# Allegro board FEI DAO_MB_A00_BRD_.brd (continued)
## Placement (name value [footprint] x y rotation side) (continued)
PC1190  -  [C_0402NEW]  119.39 57.59 180 top
PC1191  -  [C_0402NEW]  119.37 60.69 90 top
PC1192  -  [C_0402NEW]  116.06 59.85 90 top
PC1193  -  [C_0402NEW]  120.13 46.74 270 top
PC1194  -  [C_0402NEW]  121.98 44.97 270 top
PC1195  -  [C_0402NEW]  118.55 44.97 270 top
PC1196  -  [C_0402NEW]  120.44 42.34 270 top
PC1197  -  [C_0402NEW]  117.09 59.13 270 top
PC1198  -  [C_0402NEW]  117.09 57.35 270 top
PC1199  -  [C_0402NEW]  118.55 46.74 270 top
PC1200  -  [C_0402NEW]  120.13 44.97 270 top
PC1201  -  [C_0402NEW]  121.98 46.74 270 top
PC1202  -  [C_0402NEW]  130.17 48.94 90 top
PC1203  -  [C_0402NEW]  127.06 55.44 270 top
PC1204  -  [C_0402NEW]  130.17 53.67 270 top
PC1205  -  [C_0402NEW]  130.17 55.44 270 top
PC1206  -  [C_0402NEW]  128.83 50.81 270 top
PC1207  -  [C_0402NEW]  130.17 51.63 270 top
PC1208  -  [C_0402NEW]  127.12 51.82 270 top
PC1209  -  [C_0402NEW]  127.12 53.6 270 top
PC1210  -  [C_0402NEW]  127.12 50.05 270 top
PC1211  -  [C_0402NEW]  128.86 55.51 270 top
PC1212  -  [C_0402NEW]  128.86 49.06 270 top
PC1213  -  [C_0402NEW]  128.86 53.73 270 top
PC1214  -  [C_0402NEW]  125.63 55.47 270 top
PC1215  -  [C_0402NEW]  125.63 53.69 270 top
PC1216  -  [C_0402NEW]  125.63 51.91 270 top
PC1217  -  [C_0402NEW]  125.63 50.07 270 top
PC1301  -  [C_0402NEW]  26.24 26.64 0 top
PC1302  -  [C_0402NEW]  26.22 24.77 0 top
PC1303  -  [C_0402NEW]  37.56 13.73 90 top
PC1304  -  [C_0402NEW]  37.64 15.58 180 top
PC1305  -  [C_0402NEW]  36.67 14.64 270 top
PC1306  -  [C_0603NEW]  28.63 16.22 270 top
PC1307  -  [C_0402NEW]  38.56 17.04 0 top
PC1309  -  [C_0603NEW]  35.59 15.52 270 top
PC1310  -  [C_0402NEW]  34.12 12.86 180 top
PC1311  -  [C_0603NEW]  29.75 17.93 180 top
PC1312  -  [C_0402NEW]  24.99 27.63 0 top
PC1313  -  [C_0402NEW]  26.24 25.71 0 top
PC1314  -  [C_0805NEW]  20.92 25.37 180 top
PC1315  -  [C_0805NEW]  20.92 23.58 180 top
PC1316  -  [C_0402NEW]  30.42 5.27 270 bottom
PC1317  -  [C_0402NEW]  30.32 15.69 270 top
PC1318  -  [C_0402NEW]  42.83 18.68 90 top
PC1319  -  [C_0402NEW]  33.18 15.28 270 top
PC1320  -  [C_0402NEW]  40.85 19.64 0 top
PC1321  -  [C_0402NEW]  41.94 21.75 270 top
PC1322  -  [C_0402NEW]  23.25 21.17 0 top
PC1323  -  [C_0402NEW]  38.44 23.58 0 top
PC1324  -  [C_0402NEW]  41.38 22.82 180 top
PC1325  -  [C_0402NEW]  40.8 20.84 90 top
PC1326  -  [C_0402NEW]  40.67 17.56 270 top
PC1327  -  [C_0603NEW]  38.46 19.14 0 top
PC1328  -  [C_0402NEW]  39.46 21.62 270 top
PC1329  -  [C_0402NEW]  61.63 8.96 90 bottom
PC1330  -  [C_0805NEW]  63.02 8.46 90 bottom
PC1331  -  [C_0805NEW]  26.13 14.72 180 bottom
PC1332  -  [C_0805NEW]  26.13 12.88 180 bottom
PC1333  -  [C_0402NEW]  29.57 22.63 180 top
PC1334  -  [C_0402NEW]  28.68 20.81 0 top
PC1335  -  [C_0402NEW]  28.66 23.58 0 top
PC1336  -  [C_0402NEW]  32.33 5.27 270 bottom
PC1337  -  [C_0402NEW]  31.36 5.27 270 bottom
PC1338  -  [C_0402NEW]  18.18 11.71 90 bottom
PC1339  -  [C_0402NEW]  9.12 7.64 90 bottom
PC1340  -  [C_0402NEW]  11.13 4.35 0 bottom
PC1341  -  [C_0402NEW]  35.58 5.42 0 top
PC1342  -  [C_0402NEW]  39.83 27.71 0 top
PD4  -  [BAS40CW_SOT323-3]  311.37 6.94 90 top
PD5  -  [PESD24VS2UT_SOT23-3]  55.21 7.11 0 top
PD6  -  [PESD24VS2UT_SOT23-3]  51.21 8.62 180 top
PD7  -  [PESD24VS2UT_SOT23-3]  32.31 83.97 270 top
PD100  -  [LL34]  248.83 12.28 0 bottom
PD1301  -  [RB751V-40_SOD323-2]  36.26 11.64 0 top
PH700  -  [R_0402NEW]  115.26 90.31 90 bottom
PH701  -  [R_0402NEW]  123.68 85.02 90 top
PH702  -  [R_0402NEW]  154.84 76.18 270 bottom
PH703  -  [R_0402NEW]  140.42 68.54 180 bottom
PJP3  -  [JUMP_43X79]  235.35 43.11 180 top
PJP19  -  [JUMP_43X79]  148.99 6.02 0 bottom
PJP20  -  [JUMP_43X118]  133.48 13.63 90 bottom
PJP21  -  [JUMP_43X39]  138.54 3.06 0 bottom
PJP60  -  [JUMP_43X39]  41.59 38.58 180 top
PJP61  -  [JUMP_43X39]  253.14 46.54 0 bottom
PJP62  -  [JUMP_43X39]  31.37 45.4 0 top
PJP101  -  [JUMP_43X118]  221.87 4.68 180 bottom
PJP103  -  [JUMP_43X118]  263.58 12.58 0 bottom
PJP200  -  [JUMP_43X79]  26.19 58.99 270 top
PJP201  -  [JUMP_43X118]  43.91 55.08 180 top
PJP203  -  [JUMP_43X39]  35.87 59.7 90 top
PJP204  -  [JUMP_43X39]  39.15 59.62 180 top
PJP300  -  [JUMP_43X79]  103.98 13.78 270 bottom
PJP301  -  [JUMP_43X79]  94.16 5.8 180 bottom
PJP400  -  [JUMP_43X79]  154.46 73.34 270 top
PJP401  -  [JUMP_43X79]  155.51 48.12 0 bottom
PJP500  -  [JUMP_43X79]  130.06 5.55 180 top
PJP501  -  [JUMP_43X79]  114.13 16.31 270 bottom
PJP502  -  [JUMP_43X79]  115.87 12.1 180 bottom
PJP702  -  [JUMP_43X39]  118.74 88.25 90 top
PJP801  -  [JUMP_43X39]  35.97 24.04 90 top
PJPDC1  -  [ACES_50299-00501-003_5P]  23.2 70.2 180 bottom
PL2  -  [TAIYO_FBMJ4516HS720NT_2P]  58.76 6.63 0 bottom
PL4  -  [MURAT_BLM18BD102SN1D_L0603_2P]  33.9 81.11 180 top
PL5  -  [TAIYO_FBMJ4516HS720NT_2P]  23.15 67.97 180 top
PL6  -  [TAIYO_FBMJ4516HS720NT_2P]  17.3 73.62 0 top
PL15  -  [TAI-T_VMPI0703AR-1R0M-Z01_2P]  139.07 7.77 180 bottom
PL100  -  [TAI-T_HCB2012KF-121T50_2P]  216.62 5.16 90 bottom
PL101  -  [TOKO_FDSD0630-H-4R7M-P3_2P]  261.15 7.45 180 bottom
PL103  -  [TOKO_FDSD0630-H-4R7M-P3_2P]  230.97 8.7 180 bottom
PL200  -  [TAI-T_VMPI0703AR-1R0M-Z01_2P]  23.4 58.59 90 bottom
PL301  -  [TAIYO_NRS4018T1R0NDGJ_2P]  100.29 5.42 0 bottom
PL400  -  [TAI-T_VMPI0703AR-1R0M-Z01_2P]  154.59 58.67 270 bottom
PL500  -  [TAI-T_VMPI0703AR-1R0M-Z01_2P]  120.9 6.07 180 bottom
PL700  -  [TAI-T_HCB2012KF-121T50_2P]  116.66 87.25 90 top
PL702  -  [CYNTE_PDME064T-R36MS1R405_4P]  140.29 65.24 0 bottom
PL704  -  [CYNTE_PDME064T-R36MS1R405_4P]  119.53 85.52 90 bottom
PL1300  -  [TAIYO_NRS4018T1R0NDGJ_2P]  22.93 25.55 0 bottom
PL1301  -  [TOKO_FDSD0630-H-4R7M-P3_2P]  19.33 19.14 0 bottom
PQ2  -  [FDV301N_NL_SOT23-3]  37.37 81.07 180 top
PQ3  -  [MMST3904-7-F_SOT323-3]  34.64 77.24 90 top
PQ4  -  [TP0610K-T1-E3_SOT23-3]  40.85 72.98 90 top
PQ5  -  [FDS6679AZ_SO8]  18.17 65.68 270 bottom
PQ6  -  [L2N7002WT1G_SC70-3]  34.38 72.86 270 top
PQ100  -  [SI7326DN-T1-E3_PAK1212-8]  259.14 10.06 0 top
PQ101  -  [SI7326DN-T1-E3_PAK1212-8]  238.15 7.76 90 bottom
PQ102  -  [SI7326DN-T1-E3_PAK1212-8]  257.41 12.92 180 top
PQ103  -  [SI7326DN-T1-E3_PAK1212-8]  233.84 11.52 0 bottom
PQ104  -  [2N7002DW-T-R7_SOT363-6]  242.18 14.9 270 top
PQ105  -  [DTC115EUA_SC70-3]  244.04 18.5 270 top
PQ200  -  [SI7326DN-T1-E3_PAK1212-8]  24.56 62.93 270 top
PQ210  -  [SI7326DN-T1-E3_PAK1212-8]  29.03 64.56 90 top
PQ400  -  [SI7326DN-T1-E3_PAK1212-8]  155.05 58.25 0 top
PQ405  -  [SI7326DN-T1-E3_PAK1212-8]  154.36 56.6 270 top
PQ500  -  [SI7326DN-T1-E3_PAK1212-8]  120.51 7.3 270 top
PQ501  -  [SI7326DN-T1-E3_PAK1212-8]  116.9 3.85 0 top
PQ704  -  [MDU1516URH_POWERDFN56-8-5]  149.04 70.06 90 bottom
PQ706  -  [SI7170DP-T1-GE3_POWERPAK8-5]  143.1 75.46 0 bottom
PQ708  -  [MDU1516URH_POWERDFN56-8-5]  125 89.18 270 top
PQ710  -  [SI7170DP-T1-GE3_POWERPAK8-5]  124.36 92.21 0 bottom
PQ711  -  [SI7170DP-T1-GE3_POWERPAK8-5]  129.7 91.97 0 bottom
PQ1300  -  [SI7121DN-T1-GE3_POWERPAK8-5]  19 59.42 90 top
PQ1301  -  [FDS6679AZ_SO8]  70.87 8.53 270 bottom
PQ1304  -  [SI7716ADN-T1-GE3_POWERPAK8-5]  22.83 23.58 0 top
PQ1305  -  [SI7716ADN-T1-GE3_POWERPAK8-5]  19.25 21.76 270 top
PQ1306  -  [2N7002DW-T-R7_SOT363-6]  35.11 28.1 270 top
PQ1307  -  [2N7002DW-T-R7_SOT363-6]  44.22 28.91 180 top
PQ1311  -  [2N7002DW-T-R7_SOT363-6]  28.38 74.59 270 top
PR1  -  [R_0402NEW]  311.13 8.85 180 top
PR6  -  [R_0402NEW]  52.69 4.59 180 top
PR7  -  [R_0402NEW]  56.62 5.36 180 top
PR8  -  [R_0402NEW]  49.99 4.59 0 top
PR9  -  [R_0402NEW]  53.93 5.36 0 top
PR11  -  [R_0402NEW]  39.85 80.87 270 top
PR12  -  [R_0402NEW]  40.73 78.18 90 top
PR13  -  [R_0402NEW]  39.85 79.09 270 top
PR14  -  [R_0402NEW]  32.72 79.84 0 top
PR15  -  [R_0402NEW]  36.68 76.22 180 top
PR16  -  [R_0402NEW]  33.64 78.95 180 top
PR17  -  [R_0402NEW]  35.77 77.24 0 top
PR19  -  [R_0402NEW]  35.59 72.27 90 top
PR20  -  [R_0402NEW]  35.9 74.51 0 top
PR21  -  [R_0402NEW]  16.61 69.53 180 top
PR22  -  [R_0402NEW]  14.15 64.67 180 top
PR23  -  [R_0402NEW]  13.83 69.53 0 top
PR24  -  [R_0805NEW]  19.8 70.13 0 top
PR25  -  [R0402_0OHM-NEW]  33.38 74.64 180 top
PR79  -  [R_0402NEW]  143.55 13.04 270 bottom
PR80  -  [R0402_0OHM-NEW]  144.5 13.04 270 bottom
PR82  -  [R_0402NEW]  145.34 13.01 0 bottom
PR83  -  [R0402_0OHM-NEW]  141.89 12.14 90 bottom
PR84  -  [R_0603NEW]  140.94 12.34 180 bottom
PR85  -  [R_1206NEW]  135.35 3.01 180 bottom
PR86  -  [R_0402NEW]  140.63 2.87 90 bottom
PR87  -  [R_0402NEW]  143.1 2.87 90 bottom
PR88  -  [R0402_0OHM-NEW]  141.52 3.78 270 bottom
PR89  -  [R_0402NEW]  144.87 3.78 270 bottom
PR90  -  [R0402_0OHM-NEW]  143.29 14.42 90 bottom
PR91  -  [R0402_0OHM-NEW]  142.4 14.42 90 bottom
PR100  -  [R0402_0OHM-NEW]  252.66 6.17 90 bottom
PR101  -  [R_0402NEW]  251.12 4.38 90 bottom
PR102  -  [R_0402NEW]  247.31 5.29 270 bottom
PR103  -  [R_0402NEW]  250.17 4.38 90 bottom
PR104  -  [R_0402NEW]  249.15 5.29 270 bottom
PR105  -  [R_0402NEW]  250.22 8.26 270 bottom
PR106  -  [R_0402NEW]  247.92 7.35 90 bottom
PR107  -  [R_0603NEW]  254.75 7.91 180 top
PR108  -  [R_0603NEW]  245.2 7.92 180 top
PR109  -  [R_1206NEW]  256.46 12.32 180 bottom
PR110  -  [R_1206NEW]  228.47 13.31 0 bottom
PR111  -  [R_0402NEW]  249.9 15.12 90 top
PR112  -  [R_0402NEW]  244.95 6.87 180 top
PR113  -  [R_0402NEW]  251.5 14.18 180 top
PR114  -  [R_0402NEW]  245.59 15.15 270 top
PR115  -  [R_0402NEW]  246.86 17.79 90 top
PR116  -  [R0402_0OHM-NEW]  247.74 17.79 90 top
PR200  -  [R_0603NEW]  33.39 64.5 0 top
PR201  -  [R_0402NEW]  37.23 69.05 0 top
PR202  -  [R_0603NEW]  42.07 69.99 0 top
PR203  -  [R_1206NEW]  28.83 68.51 0 top
PR204  -  [R_0402NEW]  42.84 68.16 180 top
PR205  -  [R_0402NEW]  42.84 67.08 180 top
PR206  -  [R_0402NEW]  42.91 64.28 180 top
PR232  -  [R0402_0OHM-NEW]  42.91 65.24 180 top
PR236  -  [R0402_0OHM-NEW]  42.91 63.33 180 top
PR237  -  [R_0402NEW]  40.48 61.38 0 top
PR238  -  [R_0402NEW]  42.91 62.44 180 top
PR300  -  [R_0402NEW]  97.43 4.98 0 top
PR301  -  [R_0603NEW]  100.09 2.52 0 bottom
PR302  -  [R_0402NEW]  95.51 3.27 180 bottom
PR303  -  [R_0402NEW]  97.82 2.49 90 top
PR304  -  [R_0402NEW]  97.16 3.29 270 bottom
PR305  -  [R_0402NEW]  93.66 3.29 270 bottom
PR306  -  [R0402_0OHM-NEW]  98.77 2.49 90 top
PR307  -  [R_0402NEW]  124.8 8.47 0 top
PR400  -  [R_0402NEW]  155.69 68.82 270 bottom
PR401  -  [R_0603NEW]  153.7 62.76 270 bottom
PR402  -  [R_0402NEW]  156.58 68.82 270 bottom
PR403  -  [R0402_0OHM-NEW]  161.7 74.2 0 bottom
PR404  -  [R_1206NEW]  159.39 60.89 270 bottom
PR405  -  [R_0402NEW]  159.61 67.89 90 bottom
PR406  -  [R_0402NEW]  158.67 68.82 270 bottom
PR407  -  [R_0402NEW]  157.76 68.81 270 bottom
PR408  -  [R_0402NEW]  161.7 76.04 0 bottom
PR409  -  [R_0402NEW]  161.7 75.12 0 bottom
PR410  -  [R_0402NEW]  72.54 4.72 0 bottom
PR500  -  [R_0402NEW]  128.42 8.66 0 top
PR501  -  [R_0402NEW]  128.69 10.06 180 top
PR502  -  [R_0603NEW]  121.63 9.1 180 top
PR503  -  [R0402_0OHM-NEW]  127.49 8.47 180 top
PR504  -  [R_1206NEW]  124.05 7.34 270 bottom
PR505  -  [R_0402NEW]  127.78 12.79 0 top
PR507  -  [R_0402NEW]  128.69 11.9 180 top
PR508  -  [R0402_0OHM-NEW]  129.56 11.9 0 top
PR510  -  [R_0402NEW]  128.69 10.94 180 top
PR513  -  [R0402_0OHM-NEW]  129.56 11.01 0 top
PR514  -  [R_0402NEW]  129.56 10.06 0 top
PR701  -  [R_0402NEW]  138.52 88.17 270 top
PR702  -  [R_0402NEW]  137.64 92.17 270 bottom
PR703  -  [R_0402NEW]  137.74 89.1 270 bottom
PR704  -  [R_0402NEW]  136.73 90.38 0 bottom
PR705  -  [R_0402NEW]  136.86 86.32 0 bottom
PR707  -  [R_0402NEW]  140.25 92.1 180 bottom
PR708  -  [R_0402NEW]  150.78 80.43 270 bottom
PR709  -  [R_0402NEW]  139.3 91.19 270 bottom
PR710  -  [R_0402NEW]  139.74 89.37 270 bottom
PR711  -  [R_0402NEW]  140.7 89.37 0 bottom
PR712  -  [R_0402NEW]  143.47 86.15 90 top
PR713  -  [R0402_0OHM-NEW]  143.93 93.57 270 bottom
PR714  -  [R0402_0OHM-NEW]  144.62 79.66 270 bottom
PR715  -  [R_0402NEW]  144.37 87.09 270 top
PR716  -  [R0402_0OHM-NEW]  143.83 90.42 270 bottom
PR717  -  [R_0603NEW]  142.27 79.97 270 bottom
PR718  -  [R0402_0OHM-NEW]  144.72 89.57 270 bottom
PR719  -  [R0402_0OHM-NEW]  145.67 89.57 270 bottom
PR720  -  [R_0603NEW]  143.54 78.57 90 bottom
PR721  -  [R0402_0OHM-NEW]  148.23 88.25 180 top
PR722  -  [R_0402NEW]  146.55 90.37 270 bottom
PR723  -  [R0402_0OHM-NEW]  147.5 90.37 270 bottom
PR724  -  [R_0402NEW]  152.52 88.21 90 bottom
PR725  -  [R_0402NEW]  146.2 85.94 0 top
PR726  -  [R0402_0OHM-NEW]  149.89 80.43 270 bottom
PR727  -  [R_0402NEW]  146.2 86.83 0 top
PR728  -  [R_0402NEW]  151.67 80.43 270 bottom
PR729  -  [R_0402NEW]  142.12 90.28 90 bottom
PR730  -  [R_0402NEW]  143.4 88.66 90 top
PR732  -  [R0402_0OHM-NEW]  149.78 89.94 180 bottom
PR735  -  [R_0402NEW]  144.72 88.66 90 top
PR736  -  [R_0402NEW]  153.13 82.69 90 bottom
PR737  -  [R_0402NEW]  145.67 88.66 90 top
PR740  -  [R_0402NEW]  151.34 83.59 0 bottom
PR741  -  [R_0402NEW]  150.48 83.59 180 bottom
PR742  -  [R_0402NEW]  150.4 82.73 270 top
PR744  -  [R_0402NEW]  150.45 83.65 0 top
PR746  -  [R_0402NEW]  149.84 88.22 180 bottom
PR747  -  [R_0402NEW]  150.72 89.13 270 bottom
PR749  -  [R_0603NEW]  148.81 79.27 90 bottom
PR750  -  [R_0402NEW]  150.86 86.45 180 bottom
PR751  -  [R_1206NEW]  140.52 76.01 90 bottom
PR754  -  [R_0402NEW]  149.94 87.34 0 bottom
PR755  -  [R_0603NEW]  154.86 88.63 270 bottom
PR757  -  [R_0402NEW]  153.64 86.43 90 bottom
PR758  -  [R_0603NEW]  139.1 93.24 180 bottom
PR759  -  [R_0402NEW]  143.03 93.57 270 bottom
PR760  -  [R_1206NEW]  127.69 84.52 0 bottom
PR763  -  [R_0603NEW]  139.03 81.24 0 bottom
PR1301  -  [R_1206_4P-D]  23.49 57.43 180 top
PR1303  -  [R_0402NEW]  21.44 55.65 180 top
PR1304  -  [R_0402NEW]  20.54 54.77 270 top
PR1305  -  [R_0402NEW]  21.49 54.77 270 top
PR1306  -  [R_0402NEW]  29.61 75.65 0 top
PR1307  -  [R_0402NEW]  26.71 73.17 180 top
PR1308  -  [R_0402NEW]  26.71 74.06 180 top
PR1310  -  [R_0402NEW]  28.44 5.27 270 bottom
PR1311  -  [R_0402NEW]  29.49 5.27 270 bottom
PR1313  -  [R_0402NEW]  38.56 16.02 0 top
PR1316  -  [R_0402NEW]  27.51 4.37 90 bottom
PR1317  -  [R_0402NEW]  38.56 18.06 0 top
PR1318  -  [R_0603NEW]  34.32 15.52 270 top
PR1319  -  [R_0603NEW]  38.64 13.1 90 top
PR1320  -  [R0402_0OHM-NEW]  26.59 4.37 90 bottom
PR1322  -  [R_0603NEW]  31.4 14.48 90 top
PR1323  -  [R_0402NEW]  43.08 21.75 270 top
PR1324  -  [R_0402NEW]  41.76 18.63 180 top
PR1325  -  [R_0402NEW]  43.16 22.82 180 top
PR1326  -  [R_1206_4P-D]  27.32 15.07 0 bottom
PR1327  -  [R_0402NEW]  38.51 20.71 90 top
PR1328  -  [R_0402NEW]  30.96 24.01 90 top
PR1329  -  [R_0402NEW]  38.44 22.52 0 top
PR1330  -  [R_0402NEW]  29.57 21.74 180 top
PR1331  -  [R0402_0OHM-NEW]  28.66 24.47 0 top
PR1332  -  [R_1206NEW]  25.68 19.33 90 top
PR1333  -  [R_0402NEW]  9.11 5.88 90 bottom
PR1334  -  [R_0402NEW]  18.45 7.12 90 bottom
PR1335  -  [R_0402NEW]  18.18 10.84 270 bottom
PR1336  -  [R_0402NEW]  11.16 8.56 270 bottom
PR1338  -  [R_0402NEW]  10.12 5.88 90 bottom
PR1339  -  [R0402_0OHM-NEW]  43.29 30.92 180 top
PR1340  -  [R_0402NEW]  11.13 2.97 0 bottom
PR1341  -  [R_0402NEW]  36.49 4.53 180 top
PR1342  -  [R0402_0OHM-NEW]  11.14 6.8 270 bottom
PR1343  -  [R_0402NEW]  9.35 4.35 0 bottom
PR1346  -  [R_0402NEW]  19.07 11.71 90 bottom
PR1347  -  [R_0402NEW]  10.14 7.64 90 bottom
PR1348  -  [R_0402NEW]  12.03 6.8 270 bottom
PR1349  -  [R_0402NEW]  35.59 3.65 270 top
PR1350  -  [R_0402NEW]  36.5 3.67 270 top
PR1351  -  [R_0402NEW]  38.42 28.41 270 top
PU7  -  [TPS51461RGER_QFN24_4X4]  145.56 6.06 180 bottom
PU100  -  [RT8205EGQW_WQFN24_4X4]  248.27 7.45 0 top
PU200  -  [RT8207MZQW_WQFN20_3X3]  37.61 63.25 0 top
PU300  -  [SY8033BDBC_DFN10_3X3]  98.7 6.63 270 bottom
PU400  -  [TPS51218DSCR_SON10_3X3]  155.94 66.64 0 bottom
PU500  -  [TPS51218DSCR_SON10_3X3]  126.21 10.14 90 top
PU700  -  [ISL95835HRTZ-T_TQFN40_5X5]  142.59 86.94 0 bottom
PU1300  -  [BQ24745RHDR_QFN28_5X5]  36.09 18.52 90 top
PU1302  -  [74AHC1G08GW_SOT353-5]  39.68 26.56 270 top
PU1304  -  [LM393DR_SO8]  17.11 3.09 180 bottom
PWRSW1  -  [SHORTPADS]  309.85 46.38 90 top
Q12  -  [MMBT3904WT1G_SC70-3]  122.97 52.35 0 top
Q13  -  [MMBT3904WT1G_SC70-3]  124.24 82.19 90 bottom
Q14  -  [MMBT3904WT1G_SC70-3]  67.63 37.89 90 top
Q16  -  [PMST3904_SOT323-3]  169.25 95.14 180 bottom
Q18  -  [SI3456DDV-T1-GE3_TSOP6]  138.25 101.78 270 bottom
Q19  -  [DMN66D0LDW-7_SOT363-6]  135.28 98.21 270 bottom
Q20  -  [PDTC124EU_SC70-3]  136.33 97.56 270 bottom
Q21  -  [FDC654P-G_SSOT-6]  145.25 101.78 270 bottom
Q22  -  [SSM3K7002FU_SC70-3]  146.91 98.38 90 bottom
Q23  -  [PMV65XP_SOT23-3]  152.23 107.85 90 bottom
Q26  -  [SSM3K7002FU_SC70-3]  65.24 88.16 270 bottom
Q34  -  [SI3456DDV-T1-GE3_TSOP6]  310.24 44.19 90 bottom
Q35  -  [DMN66D0LDW-7_SOT363-6]  305.48 46.22 0 bottom
Q38  -  [SI3456DDV-T1-GE3_TSOP6]  237.42 55.7 0 bottom
Q39  -  [DMN66D0LDW-7_SOT363-6]  234.1 56.06 0 bottom
Q40  -  [SI3456DDV-T1-GE3_TSOP6]  311.67 36.92 180 top
Q41  -  [DMN66D0LDW-7_SOT363-6]  315.74 35.56 90 top
Q42  -  [SI3456DDV-T1-GE3_TSOP6]  239.91 48.1 270 bottom
Q43  -  [DMN66D0LDW-7_SOT363-6]  238.88 50.98 270 bottom
Q45  -  [SSM3K7002FU_SC70-3]  295.75 66.51 270 top
Q47  -  [SSM3K7002FU_SC70-3]  275.49 47.27 0 top
Q48  -  [SSM3K7002FU_SC70-3]  307.96 65.27 270 bottom
Q49  -  [SI3456DDV-T1-GE3_TSOP6]  203.85 4.63 270 bottom
Q50  -  [SSM3K7002FU_SC70-3]  282.88 68.4 180 top
Q51  -  [DMN66D0LDW-7_SOT363-6]  208.5 2.51 180 bottom
Q52  -  [DMN66D0LDW-7_SOT363-6]  178.95 3.78 270 bottom
Q53  -  [SSM3K7002FU_SC70-3]  306.2 57.63 270 bottom
Q55  -  [DMN3030LSS-13_SOP8L-8]  188.19 11.29 90 bottom
Q56  -  [SSM3K7002FU_SC70-3]  232.06 53.49 180 bottom
Q57  -  [DMN66D0LDW-7_SOT363-6]  165.06 80.56 270 bottom
Q58  -  [SI3456DDV-T1-GE3_TSOP6]  168.99 79.64 180 bottom
Q59  -  [AO4728L_SO8]  187.56 7.64 270 bottom
Q60  -  [SSM3K7002FU_SC70-3]  163.48 83.65 270 bottom
Q61  -  [DMN3030LSS-13_SOP8L-8]  229.03 47.46 90 bottom
Q62  -  [SSM3K7002FU_SC70-3]  186.95 16.71 180 bottom
Q63  -  [SI4164DY-T1-GE3_SO8]  137.72 42 90 bottom
Q64  -  [SSM3K7002FU_SC70-3]  140.55 43.23 270 top
Q66  -  [SSM3K7002FU_SC70-3]  198.21 11.77 90 top
Q67  -  [SSM3K7002FU_SC70-3]  185.96 23.46 180 bottom
Q68  -  [SSM3K7002FU_SC70-3]  202.83 10.51 270 bottom
Q69  -  [SSM3K7002FU_SC70-3]  224.57 47.84 180 bottom
Q70  -  [SSM3K7002FU_SC70-3]  139.54 26.78 270 bottom
Q71  -  [SSM3K7002FU_SC70-3]  102.77 11.16 90 top
Q72  -  [SSM3K7002FU_SC70-3]  31.91 87.14 270 bottom
Q73  -  [SSM3K7002FU_SC70-3]  315.85 32.19 90 top
Q74  -  [DMN66D0LDW-7_SOT363-6]  168.61 67.08 0 bottom
Q75  -  [PDTA114EU_SC70-3]  165.41 62.95 90 bottom
Q77  -  [SSM3K7002FU_SC70-3]  254.51 50.6 180 bottom
Q78  -  [DMN66D0LDW-7_SOT363-6]  163.59 72.22 0 bottom
Q79  -  [PDTA114EU_SC70-3]  164.24 66.47 180 bottom
Q80  -  [DMN66D0LDW-7_SOT363-6]  166.2 72.16 0 bottom
Q81  -  [PDTA114EU_SC70-3]  166.72 66.47 180 bottom
Q83  -  [DMN66D0LDW-7_SOT363-6]  165.38 59.22 270 bottom
Q84  -  [DMN66D0LDW-7_SOT363-6]  162.26 65.23 0 bottom
Q107  -  [DMN66D0LDW-7_SOT363-6]  19.77 37.91 0 top
Q120  -  [DMN66D0LDW-7_SOT363-6]  98 88.8 180 bottom
Q121  -  [SSM3K7002FU_SC70-3]  80.82 92.85 90 bottom
Q124  -  [DMN66D0LDW-7_SOT363-6]  235.85 64.87 0 bottom
Q126  -  [SSM3K7002FU_SC70-3]  246.86 48.42 180 bottom
Q127  -  [PDTC124EU_SC70-3]  289.3 69.09 90 top
QC1  -  [SSM3K7002FU_SC70-3]  108.3 81.05 90 top
QC2  -  [BSS138W-7-F_SOT323-3]  134.11 20.06 90 top
QC3  -  [AO4728L_SO8]  100.85 15.14 270 bottom
QC4  -  [DMN66D0LDW-7_SOT363-6]  101.95 8 90 top
QC5  -  [NTR4503NT1G_SOT23-3]  102.77 78.61 0 top
QD1  -  [BSS138-G_SOT23-3]  72.83 14.87 0 bottom
QD2  -  [BSS138-G_SOT23-3]  78.25 13.9 270 bottom
QH4  -  [SSM3K7002FU_SC70-3]  191.5 18.2 180 bottom
QH5  -  [DMN66D0LDW-7_SOT363-6]  182.57 22.41 180 bottom
QH6  -  [DMN66D0LDW-7_SOT363-6]  179.14 37.02 180 bottom
QH7  -  [SSM3K7002FU_SC70-3]  180.59 34.35 0 bottom
QH8  -  [SSM3K7002FU_SC70-3]  190.21 21.49 270 bottom
R3  -  [R_0402NEW]  260.6 84.02 270 top
R159  -  [C_0402NEW]  106.24 89.86 90 bottom
R160  -  [R_0402NEW]  105.35 89.86 90 bottom
R385  -  [R_0402NEW]  165.8 106.29 180 bottom
R387  -  [R_0402NEW]  154.75 103.63 180 bottom
R388  -  [R_0402NEW]  156.06 108.2 270 bottom
R389  -  [R_0402NEW]  165.8 102.68 180 bottom
R390  -  [R_0402NEW]  165.8 99.08 180 bottom
R391  -  [R_0402NEW]  165.8 103.63 180 bottom
R393  -  [R_0402NEW]  154.69 104.58 180 bottom
R395  -  [R_0402NEW]  169.77 97.03 180 bottom
R399  -  [R_0402NEW]  167.46 96.12 270 bottom
R402  -  [R_0402NEW]  165.8 100.9 180 bottom
R403  -  [R_0402NEW]  164.89 101.79 0 bottom
R404  -  [R_0402NEW]  164.89 104.52 0 bottom
R406  -  [R_0402NEW]  154.82 101.79 180 bottom
R412  -  [R_0402NEW]  137.2 95.84 180 bottom
R413  -  [R_0402NEW]  133.58 99.2 180 bottom
R414  -  [R_0402NEW]  132.7 100.96 270 bottom
R418  -  [R_0402NEW]  299.53 54.99 180 top
R420  -  [R_0402NEW]  299.53 55.88 180 top
R422  -  [R_0402NEW]  143.69 97.72 0 bottom
R423  -  [R_0402NEW]  145.46 98.61 270 bottom
R426  -  [R_0402NEW]  165.8 105.41 180 bottom
R427  -  [R_0402NEW-S]  102.34 89.62 180 bottom
R428  -  [R_0402NEW-S]  102.34 88.73 180 bottom
R448  -  [R_0402NEW]  67.4 93.07 270 bottom
R449  -  [R_0402NEW]  70.08 93.07 270 bottom
R450  -  [R_0402NEW]  67.21 95.29 270 bottom
R452  -  [R_0402NEW]  64.55 95.29 270 bottom
R453  -  [R_0402NEW]  77.95 95.67 270 bottom
R454  -  [R_0402NEW]  75.28 95.67 270 bottom
R455  -  [R_0402NEW]  74.06 95.67 270 bottom
R456  -  [R_0402NEW]  71.39 95.67 270 bottom
R457  -  [R_0402NEW]  258.13 66.91 90 top
R458  -  [R_0402NEW]  61.17 87.51 0 bottom
R545  -  [R_0402NEW]  285.25 87.57 270 top
R546  -  [R_0402NEW]  283.86 87.57 270 top
R547  -  [R_0402NEW]  281.65 76.74 90 top
R548  -  [R_0805NEW]  292.92 83.46 90 top
R549  -  [R_0402NEW]  286.26 76.73 180 top
R551  -  [R0402_0OHM-NEW]  287.98 87.57 270 top
R552  -  [R0402_0OHM-NEW]  286.2 87.57 270 top
R553  -  [R_0402NEW]  282.57 75.8 90 top
R554  -  [R_0402NEW]  283.49 75.8 90 top
R555  -  [R0402_0OHM-NEW]  282.15 69.68 0 top
R557  -  [R_0402NEW]  283.93 69.68 0 top
R561  -  [R_0402NEW]  287.09 86.66 90 top
R562  -  [R_0402NEW]  289.78 77 0 top
R563  -  [R_1206NEW]  315.65 44.45 0 bottom
R564  -  [R_0402NEW]  307.84 44.31 90 bottom
R565  -  [R_0402NEW]  304.39 45.18 270 bottom
R589  -  [R_0402NEW]  278.62 47.52 180 top
R590  -  [R_0402NEW]  278.62 48.41 180 top
R591  -  [R_0402NEW]  278.62 46.63 180 top
R592  -  [R_0402NEW]  278.62 45.74 180 top
R656  -  [R_0402NEW]  258.16 50.82 180 bottom
R657  -  [R_0402NEW]  257.24 47.97 0 bottom
R658  -  [R_0402NEW]  257.24 51.71 0 bottom
R659  -  [R_0402NEW]  258.16 47.08 180 bottom
R660  -  [R_0402NEW]  258.16 52.6 180 bottom
R663  -  [R_0402NEW]  281.06 18.45 90 top
R664  -  [R_0402NEW]  282.14 18.45 90 top
R665  -  [R_0402NEW]  280.17 18.45 90 top
R668  -  [R_0402NEW]  285.93 17.19 0 top
R669  -  [R_0402NEW]  285.93 16.31 0 top
R670  -  [R_0402NEW]  285.93 15.42 0 top
R672  -  [R_0402NEW]  285.93 14.53 0 top
R673  -  [R_0402NEW]  285.93 13.64 0 top
R674  -  [R_0402NEW]  285.93 12.75 0 top
R676  -  [R_0402NEW]  285.93 11.86 0 top
R677  -  [R_0402NEW]  274.95 15.73 0 top
R692  -  [R_0402NEW]  243.55 55.17 90 bottom
R693  -  [R_0402NEW]  256.14 67.83 270 top
R694  -  [R_0402NEW]  282.19 43.38 270 top
R695  -  [R_0402NEW]  282.82 30.91 90 bottom
R697  -  [R_0402NEW]  281.04 43.38 270 top
R698  -  [R_0402NEW]  244.51 56.09 270 bottom
R699  -  [R_0402NEW]  248.84 56.03 270 bottom
R700  -  [R0402_0OHM-NEW]  270.74 63.95 0 bottom
R701  -  [R_0402NEW]  245.39 56.09 270 bottom
R702  -  [R0402_0OHM-NEW]  314.36 18.66 180 top
R703  -  [R0402_0OHM-NEW]  260.77 30.44 180 top
R704  -  [R0402_0OHM-NEW]  288.66 42.4 90 top
R705  -  [R_0402NEW]  237.28 61.95 180 bottom
R706  -  [R_0402NEW]  249.79 56.03 270 bottom
R707  -  [R0402_0OHM-NEW]  241.27 59.38 90 top
R708  -  [R_0402NEW]  262.51 23.17 90 top
R711  -  [R_0402NEW]  263.53 23.17 90 top
R712  -  [R_0402NEW]  260.7 24.04 270 top
R713  -  [R_0402NEW]  234.99 53.11 180 bottom
R714  -  [R_0402NEW]  241.55 55.11 180 bottom
R715  -  [R_0402NEW]  240.84 53.84 0 bottom
R716  -  [R_0402NEW]  234.7 57.21 180 bottom
R718  -  [R_0402NEW]  235.73 65.95 0 bottom
R719  -  [R_0402NEW]  255.33 55.54 0 bottom
R721  -  [R_0402NEW]  312.93 34.49 0 top
R722  -  [R_0402NEW]  314.37 39.1 270 top
R723  -  [R_0402NEW]  314.19 30.48 0 top
R725  -  [R_0402NEW]  281.87 30.91 90 bottom
R726  -  [R_0402NEW]  316.21 34.44 270 top
R728  -  [R_0402NEW]  235.93 48.9 90 bottom
R729  -  [R_0402NEW]  242.77 46.73 180 bottom
R730  -  [R_0402NEW]  235.91 45.87 180 bottom
R733  -  [R_0402NEW]  240.15 49.7 90 bottom
R735  -  [R0402_0OHM-NEW]  179.9 4.05 270 bottom
R736  -  [R_0402NEW-S]  308.43 61.54 0 bottom
R737  -  [R0402_0OHM-NEW]  209.64 3.41 270 bottom
R738  -  [R0402_0OHM-NEW]  265.17 67.83 270 top
R740  -  [R_0402NEW-S]  308.43 62.46 0 bottom
R741  -  [R0402_0OHM-NEW]  200.81 12.42 0 bottom
R742  -  [R0402_0OHM-NEW]  200.81 13.56 0 bottom
R743  -  [R_0402NEW]  244.25 77.92 180 top
R744  -  [R_0402NEW]  180.82 4.05 270 bottom
R745  -  [R_0402NEW]  244.25 76.92 180 top
R746  -  [R_0402NEW]  237.52 79.18 180 bottom
R747  -  [R_0402NEW]  244.25 75.89 180 top
R749  -  [R0402_0OHM-NEW]  237.52 77.28 270 bottom
R750  -  [R_0402NEW]  210.6 3.41 270 bottom
R751  -  [R0402_0OHM-NEW]  237.52 78.26 180 bottom
R752  -  [R_0402NEW]  237.54 75.01 180 bottom
R755  -  [R_0402NEW]  266.05 83.1 90 top
R759  -  [R_0402NEW]  290.7 67.13 270 top
R760  -  [R_0402NEW]  274.11 80.11 0 top
R761  -  [R_0402NEW]  255.06 80.26 0 top
R763  -  [R_0402NEW]  260.47 66.91 90 top
R764  -  [R_0402NEW]  268.03 67.83 270 top
R765  -  [R0402_0OHM-NEW]  256.14 70.63 180 top
R766  -  [R_0402NEW]  267.07 66.91 90 top
R767  -  [R_0402NEW]  266.98 84.02 270 top
R768  -  [R_0402NEW]  268.89 84.02 270 top
R769  -  [R_0402NEW]  264.28 84.02 270 top
R771  -  [R_0402NEW]  256.16 73.4 180 top
R772  -  [R_0402NEW]  256.23 78.35 180 top
R773  -  [R_0402NEW]  263.33 83.1 90 top
R774  -  [R_0402NEW]  256.23 77.4 180 top
R775  -  [R_0402NEW]  261.52 84.02 270 top
R776  -  [R_0402NEW]  259.09 66.91 90 top
R777  -  [R_0402NEW]  280.74 76.64 270 top
R778  -  [R_0402NEW]  258.63 84.02 270 top
R780  -  [R_0402NEW]  278.67 78.92 270 top
R782  -  [R_0402NEW]  277.78 78.92 270 top
R784  -  [R0402_0OHM-NEW]  304.86 65.41 270 bottom
R785  -  [R_0402NEW]  256.05 79.3 180 top
R786  -  [R_0402NEW]  266.12 66.91 90 top
R789  -  [R_0402NEW]  268.98 66.91 90 top
R790  -  [R_0402NEW]  255.25 72.51 0 top
R791  -  [R_0402NEW]  272.74 78.28 180 top
R793  -  [R_0402NEW]  264.22 67.83 270 top
R794  -  [R_0402NEW]  271.82 79.22 0 top
R795  -  [R_0402NEW]  274.12 78.24 0 top
R796  -  [R_0402NEW]  259.64 84.02 270 top
R797  -  [R0402_0OHM-NEW]  254.26 78.29 270 top
R798  -  [R_0402NEW]  272.72 80.11 180 top
R799  -  [R_0402NEW]  294.51 66.21 90 top
R800  -  [R_0402NEW]  255.31 74.74 0 top
R802  -  [R_0402NEW]  269.87 66.91 90 top
R803  -  [R_0402NEW]  256.23 75.62 180 top
R804  -  [R_0402NEW]  279.57 77.1 90 top
R805  -  [R_0402NEW]  255.06 82.16 0 top
R806  -  [R0402_0OHM-NEW]  270.06 86.15 90 top
R807  -  [R_0402NEW]  255.06 83.12 0 top
R808  -  [R_0402NEW]  271.01 87.07 270 top
R810  -  [R_0402NEW]  298.62 49.46 0 top
R811  -  [R_0402NEW]  300.41 49.45 90 top
R812  -  [R_0402NEW]  278.57 50.24 270 top
R813  -  [R_0402NEW]  296.72 50.44 180 top
R814  -  [R_0402NEW]  272.85 56.11 90 top
R815  -  [R0402_0OHM-NEW]  296.74 51.37 180 top
R816  -  [R_0402NEW]  309.24 64.5 90 bottom
R817  -  [R_0402NEW]  292.96 69.76 270 top
R818  -  [R_0402NEW]  286.82 47.01 90 top
R820  -  [R_0402NEW]  287.77 47.01 90 top
R821  -  [R_0402NEW]  295.83 60.57 0 top
R822  -  [R_0402NEW]  284.03 49.32 90 top
R823  -  [R_0402NEW]  284.52 66.23 90 top
R824  -  [R_0402NEW]  284.09 47.95 270 top
R826  -  [R_0402NEW]  282.78 8.83 270 top
R827  -  [R_0402NEW]  281.3 49.32 90 top
R828  -  [R_0402NEW]  282.19 49.32 90 top
R829  -  [R_0402NEW]  283.14 49.32 90 top
R835  -  [R_0402NEW]  286.12 50.24 270 top
R836  -  [R_0402NEW]  285.23 45.86 270 top
R838  -  [R_0402NEW]  298.6 52.28 0 top
R841  -  [R_0402NEW]  298.6 51.39 0 top
R843  -  [R_0402NEW]  281.09 67.74 270 top
R845  -  [R_0402NEW]  279.44 60.07 0 top
R846  -  [R_0402NEW]  272.89 58.81 90 top
R847  -  [R_0402NEW]  264.09 62.17 270 top
R848  -  [R_0402NEW]  266.88 60.56 90 top
R849  -  [R_0402NEW]  268.79 60.56 90 top
R850  -  [R_0402NEW]  264.98 62.17 270 top
R851  -  [R_0402NEW]  279.44 59.18 0 top
R852  -  [R_0402NEW]  279.44 60.96 0 top
R853  -  [R0402_0OHM-NEW]  265.93 60.56 90 top
R854  -  [R_0402NEW]  299.53 56.76 180 top
R855  -  [R0402_0OHM-NEW]  267.84 60.56 90 top
R856  -  [R_0402NEW]  299.53 57.65 180 top
R858  -  [R_0402NEW]  260.53 62.17 270 top
R859  -  [R_0402NEW]  261.42 62.17 270 top
R860  -  [R_0402NEW]  262.31 62.17 270 top
R861  -  [R_0402NEW]  263.2 61.26 90 top
R862  -  [R0402_0OHM-NEW]  280.36 54.67 180 top
R863  -  [R_0402NEW]  273.75 48.14 270 top
R864  -  [R_0402NEW]  259.64 62.17 270 top
R867  -  [R0402_0OHM-NEW]  288.16 49.39 90 top
R869  -  [R_0402NEW]  280.36 58.29 180 top
R870  -  [R_0402NEW]  288.73 47.95 270 top
R871  -  [R_0402NEW]  298.62 58.61 0 top
R872  -  [R_0402NEW]  295.83 53.27 0 top
R873  -  [R0402_0OHM-NEW]  256.3 48.97 90 bottom
R874  -  [R_0402NEW]  301.8 52.28 180 top
R875  -  [R_0402NEW]  298.56 60.57 0 top
R876  -  [R_0402NEW]  296.74 62.86 180 top
R877  -  [R_0402NEW]  301.8 51.39 180 top
R878  -  [R_0402NEW]  254.41 76.41 270 top
R879  -  [R_0402NEW]  296.74 52.32 180 top
R880  -  [R_0402NEW]  288.47 67.13 270 top
R881  -  [R_0402NEW]  293.96 69.76 270 top
R882  -  [R_0402NEW]  287.52 67.13 270 top
R883  -  [R_0402NEW]  110.19 21.49 0 top
R884  -  [R_0402NEW]  299.51 53.17 180 top
R885  -  [R_0402NEW]  285.74 66.21 90 top
R886  -  [R_0402NEW]  295.83 57.65 0 top
R887  -  [R_0402NEW]  292.6 67.13 270 top
R888  -  [R_0402NEW]  292.07 69.76 270 top
R889  -  [R_0402NEW]  279.44 61.91 0 top
R890  -  [R_0402NEW]  208.73 26.27 90 bottom
R891  -  [R_0402NEW]  211.52 37.87 180 bottom
R892  -  [R_0402NEW]  279.44 56.45 0 top
R893  -  [R_0402NEW]  281.06 68.77 0 top
R894  -  [R_0402NEW]  211 26.27 90 bottom
R895  -  [R_0402NEW]  211.02 24.75 0 bottom
R896  -  [R_0402NEW]  203.85 21.23 0 top
R897  -  [R_0402NEW]  214.2 13.93 180 bottom
R898  -  [R_0402NEW]  209.81 26.27 90 bottom
R899  -  [R_0402NEW]  209.28 40.45 180 bottom
R900  -  [R_0402NEW]  212.4 14.39 180 bottom
R901  -  [R_0402NEW]  207.47 37.91 90 bottom
R902  -  [R_0402NEW]  223.23 32.23 270 top
R903  -  [R_0402NEW]  225.01 32.23 270 top
R905  -  [R_0402NEW]  206.14 3.35 270 bottom
R906  -  [R_0402NEW]  198.14 21.1 90 top
R907  -  [R_0402NEW]  208.31 6.32 270 bottom
R908  -  [R_0402NEW]  200.39 10.55 0 top
R909  -  [R_0402NEW]  176.97 4.79 0 bottom
R910  -  [R_0402NEW]  189.46 9.94 0 bottom
R912  -  [R_0402NEW]  198.14 22.92 90 top
R913  -  [R_0402NEW]  229.89 45.93 0 bottom
R916  -  [R_0603NEW]  166.15 83.84 180 bottom
R917  -  [R_0402NEW]  167.16 77.2 90 bottom
R918  -  [R_0402NEW]  164 81.62 180 bottom
R919  -  [R_0402NEW]  167.47 84.99 0 bottom
R920  -  [R_0402NEW]  191.06 2.87 90 bottom
R921  -  [R_0402NEW]  192.54 9.04 90 bottom
R923  -  [R_0402NEW]  185.96 21.13 90 bottom
R924  -  [R_0402NEW]  203.5 8.71 90 bottom
R925  -  [R_0402NEW]  139.32 28.53 180 bottom
R926  -  [R_0402NEW]  102.57 12.8 0 top
R927  -  [R_0603NEW]  34.57 87.14 180 bottom
R928  -  [R_0402NEW]  200.39 11.77 180 top
R929  -  [R_0603NEW]  226.54 46.12 180 bottom
R930  -  [R_0402NEW]  140.41 44.96 0 top
R931  -  [R_0402NEW]  137.84 40.6 180 bottom
R932  -  [R_0402NEW]  169.33 68.22 180 bottom
R933  -  [R_0402NEW]  190.33 16.74 180 bottom
R935  -  [R0402_0OHM-NEW]  212.3 26.3 90 bottom
R936  -  [R0402_0OHM-NEW]  208.59 24.72 0 bottom
R937  -  [R_0402NEW]  164.04 73.3 0 bottom
R938  -  [R_0402NEW]  165.55 65.86 270 bottom
R940  -  [R_0402NEW]  229.33 53.57 270 bottom
R941  -  [R_0402NEW]  287.52 69.36 270 top
R942  -  [R_0402NEW]  286.63 69.36 270 top
R949  -  [R_0402NEW]  164.36 60.4 90 bottom
R950  -  [R_0402NEW]  164.1 69.24 0 bottom
R951  -  [R_0402NEW]  163.4 60.4 90 bottom
R955  -  [R_0402NEW]  162.27 66.94 90 bottom
R958  -  [R_0402NEW]  164.32 56.86 180 bottom
R959  -  [R_0402NEW]  166.4 59.34 270 bottom
R1068  -  [R0402_0OHM-NEW]  292.49 50.22 180 top
R1076  -  [R_0402NEW]  37.98 36.68 0 top
R1077  -  [R_0402NEW]  37.98 35.8 0 top
R1078  -  [R_0402NEW]  33.46 42.9 0 top
R1081  -  [R_0402NEW]  263.26 66.91 90 top
R1082  -  [R_0402NEW]  262.31 66.91 90 top
R1083  -  [R_0402NEW]  22.05 38.8 0 top
R1086  -  [R_0402NEW]  22.97 37.91 180 top
R1087  -  [R_0402NEW]  38.12 44.7 90 top
R1089  -  [R_0402NEW]  288.92 86.69 90 top
R1090  -  [R_0402NEW]  297.03 69.31 270 top
R1091  -  [R_0402NEW]  299.81 69.31 270 top
R1095  -  [R0805_0OHM-NEW]  43.15 32.71 180 top
R1096  -  [R_0402NEW]  38.89 37.63 180 top
R1099  -  [R_0402NEW]  41.81 36.67 270 top
R1111  -  [R_0402NEW]  313.2 74.72 0 top
R1112  -  [R_0402NEW]  313.2 76.15 0 top
R1113  -  [R_0402NEW]  313.2 82.34 0 top
R1114  -  [R_0402NEW]  313.2 83.73 0 top
R1118  -  [R_0402NEW]  295.83 56.7 0 top
R1119  -  [R_0402NEW]  39.76 42.79 0 top
R1120  -  [R_0402NEW]  39.76 40.13 0 top
R1125  -  [R_0402NEW]  291.65 67.13 270 top
R1128  -  [R_0402NEW]  79.27 92.85 180 bottom
R1137  -  [R_0402NEW]  103.99 87.63 270 top
R1138  -  [R_0402NEW]  96.98 88.96 0 top
R1141  -  [R_0402NEW]  39.76 41.02 0 top
R1142  -  [R_0402NEW]  39.76 41.91 0 top
R1143  -  [R_0402NEW]  27.46 42.58 180 top
R1144  -  [R0402_0OHM-NEW]  291.61 76.64 270 top
R1152  -  [R_0402NEW]  95.22 89.53 270 bottom
R1153  -  [R_0402NEW]  95.22 90.36 90 bottom
R1156  -  [R_0402NEW]  293.4 49.35 90 top
R1157  -  [R_0402NEW]  285.23 41.47 270 top
R1158  -  [R_0402NEW]  285.23 38.78 90 top
R1159  -  [R_0402NEW]  285.23 43.32 270 top
R1160  -  [R_0402NEW]  284.22 43.32 270 top
R1161  -  [R0603_0OHM-NEW]  206.88 8.34 270 top
R1162  -  [R_0603NEW]  215.68 7.71 180 top
R1163  -  [R0402_0OHM-NEW]  91.31 64.5 90 top
R1165  -  [R_0402NEW]  74.44 99.72 0 bottom
R1168  -  [R_0402NEW]  83.93 92.33 90 bottom
R1169  -  [R_0402NEW]  299.53 54.1 180 top
R1171  -  [R_0402NEW]  279.44 62.86 0 top
R1179  -  [R_0402NEW]  280.41 50.24 270 top
R1180  -  [R0402_0OHM-NEW]  279.52 49.32 90 top
R1187  -  [R0402_0OHM-NEW]  282.54 78.53 180 top
R1197  -  [R_0402NEW]  293.55 66.21 90 top
R1594  -  [R_0402NEW]  244.25 78.81 180 top
R1595  -  [R_0402NEW]  237.53 74.09 180 bottom
R1603  -  [R_0402NEW-S]  309.49 56.43 0 bottom
R1604  -  [R_0402NEW-S]  309.49 58.27 0 bottom
R1605  -  [R_0402NEW-S]  309.49 59.16 0 bottom
R1606  -  [R_0402NEW-S]  309.49 57.32 0 bottom
R1610  -  [R_0402NEW]  190.15 3.78 270 bottom
R1611  -  [R_0402NEW]  142.25 44.96 0 top
R1613  -  [R_0402NEW]  305.99 60.32 0 bottom
R1614  -  [R_0402NEW]  306.9 59.37 180 bottom
R1617  -  [R_0402NEW]  165.38 78.08 270 bottom
R1618  -  [R_0402NEW]  228.38 52.65 90 bottom
R1619  -  [R_0402NEW]  205.25 2.44 90 bottom
R1620  -  [R_0402NEW]  235.68 57.1 90 bottom
R1621  -  [R_0402NEW]  186.59 15 180 bottom
R1622  -  [R_0402NEW]  188.71 27.5 270 bottom
R1623  -  [R_0402NEW]  186.54 29.08 0 bottom
R1624  -  [R0402_0OHM-NEW]  186.54 30.03 0 bottom
R1625  -  [R_0402NEW]  316.15 38.19 90 top
R1626  -  [R0402_0OHM-NEW]  303.97 64.5 90 bottom
R1627  -  [R_0402NEW]  267.94 83.1 90 top
R1628  -  [R_0402NEW]  241.85 45.84 0 bottom
R1629  -  [R_0402NEW]  256.14 71.59 180 top
R1630  -  [R_0402NEW]  189.39 33.37 270 bottom
R1632  -  [R_0402NEW]  139.76 99.96 270 bottom
R1638  -  [R_0402NEW]  307.84 46.08 90 bottom
R1641  -  [R_0402NEW]  10.79 67.95 270 bottom
R1642  -  [R_0402NEW]  10.74 71.42 90 top
R1643  -  [R_0402NEW]  10.74 74.21 270 top
R1644  -  [R_0402NEW]  9.81 73.33 90 top
R1645  -  [R_0402NEW]  10.9 80.41 180 bottom
R1646  -  [R_0402NEW]  11.04 78.47 90 bottom
R1647  -  [R_0402NEW]  11.04 77.61 270 bottom
R1650  -  [R_0402NEW]  21.46 32.9 270 bottom
R1651  -  [R_0402NEW]  21.46 35.31 270 bottom
R1652  -  [R0402_0OHM-NEW]  17.48 40.35 0 bottom
R1658  -  [R_0402NEW]  32.29 27.53 270 top
R1659  -  [R_0402NEW]  33.24 27.53 270 top
R1660  -  [R_0402NEW]  31.34 27.53 270 top
R1661  -  [R_0402NEW]  30.38 27.53 270 top
R1662  -  [R0402_0OHM-NEW]  271.32 46.95 180 bottom
R1663  -  [R_0402NEW]  271.32 47.84 180 bottom
R1668  -  [R_0402NEW]  23.21 77.04 180 top
R1669  -  [R_0402NEW]  17.75 77.35 90 top
R1670  -  [R_0402NEW]  13.24 77.92 90 top
R1677  -  [R_0402NEW]  311.08 53.96 90 bottom
R1678  -  [R_0402NEW-S]  259.27 92.06 180 bottom
R1679  -  [R_0402NEW-S]  251.13 91.23 90 bottom
R1680  -  [R_0402NEW-S]  252.02 91.23 90 bottom
R1681  -  [R_0402NEW-S]  259.27 92.95 180 bottom
R1682  -  [R_0402NEW-S]  254.56 91.23 90 bottom
R1683  -  [R_0402NEW-S]  255.45 91.23 90 bottom
R1702  -  [R_0402NEW-S]  23.91 49.86 180 bottom
R1703  -  [R_0402NEW-S]  23.91 50.82 180 bottom
R1704  -  [R_0402NEW-S]  23.91 48.97 180 bottom
R1705  -  [R_0402NEW-S]  23.91 48.02 180 bottom
R1706  -  [R_0402NEW-S]  23.91 51.7 180 bottom
R1707  -  [R_0402NEW-S]  23.91 47.13 180 bottom
R1708  -  [R_0402NEW]  313.44 19.62 0 top
R1709  -  [R_0402NEW]  314.36 23.81 180 top
R1710  -  [R_0402NEW]  313.44 20.63 0 top
R1717  -  [R0402_0OHM-NEW]  253.79 66.86 90 top
R1718  -  [R_0402NEW]  238.31 70.3 90 top
R1719  -  [R_0402NEW]  238.22 80.75 90 top
R1720  -  [R_0402NEW]  239.2 70.3 90 top
R1721  -  [R_0402NEW]  239.17 80.75 90 top
R1722  -  [R_0402NEW]  240.11 70.3 90 top
R1723  -  [R_0402NEW]  240.13 80.75 90 top
R1724  -  [R_0402NEW]  241.01 70.3 90 top
R1725  -  [R_0402NEW]  241.01 80.75 90 top
R1726  -  [R_0402NEW]  253.79 63.68 270 top
R1727  -  [R_0402NEW]  253.79 61.12 270 top
R1728  -  [R_0402NEW]  259.09 64.86 270 top
R1729  -  [R_0402NEW]  268.41 64.42 270 top
R1730  -  [R_0402NEW]  270.77 63.43 0 top
R1731  -  [R_0402NEW]  166.3 58.99 180 top
R1732  -  [R_0402NEW]  162.06 59.04 90 top
R1733  -  [R_0402NEW]  161.18 59.04 90 top
R1734  -  [R_0402NEW]  247.16 51.65 180 bottom
R1735  -  [R_0402NEW]  300.21 86.9 0 top
R1736  -  [R_0402NEW]  300.21 85.95 0 top
R1737  -  [R_0402NEW]  300.34 83.96 0 top
R1738  -  [R_0402NEW]  300.34 83.02 0 top
R1739  -  [R_0402NEW]  299.79 80.76 0 top
R1740  -  [R_0402NEW]  299.79 79.83 0 top
R1741  -  [R_0402NEW]  299.74 77.66 0 top
R1742  -  [R_0402NEW]  299.74 76.72 0 top
R1743  -  [R_0402NEW]  149.19 62.2 180 top
R1744  -  [R_0402NEW]  288.4 69.36 270 top
RC1  -  [R_0402NEW]  129.95 31.95 90 bottom
RC2  -  [R_0402NEW]  121.86 32.76 180 bottom
RC4  -  [R_0402NEW]  140.05 71.19 90 bottom
RC5  -  [R_0402NEW]  93.13 89.41 180 top
RC6  -  [R0402_0OHM-NEW]  93.13 88.53 180 top
RC7  -  [R_0402NEW]  93.13 87.64 180 top
RC8  -  [R_0402NEW]  93.77 81.85 180 top
RC9  -  [R_0402NEW]  93.13 86.68 180 top
RC10  -  [R_0402NEW]  140.05 72.97 90 bottom
RC12  -  [R_0402NEW]  105.38 79.84 0 bottom
RC16  -  [R_0402NEW]  119.12 32.84 270 bottom
RC17  -  [R_0402NEW]  120.07 32.84 270 bottom
RC18  -  [R_0402NEW]  105.2 85.95 0 bottom
RC19  -  [R_0402NEW]  130.16 66.95 180 top
RC23  -  [R0402_0OHM-NEW]  133.74 80.21 90 top
RC24  -  [R0402_0OHM-NEW]  131.95 81.12 270 top
RC25  -  [R_0402NEW]  129.3 67.87 90 top
RC26  -  [R0402_0OHM-NEW]  129.9 64.98 180 top
RC27  -  [R_0402NEW]  130.17 81.12 270 top
RC28  -  [R_0402NEW]  107.69 82.88 0 top
RC29  -  [R_0402NEW]  132.85 81.12 270 top
RC32  -  [R_0402NEW]  126.95 61.08 90 top
RC35  -  [R_0402NEW]  131.06 81.12 270 top
RC40  -  [R_0402NEW]  129.08 64.06 180 top
RC41  -  [R_0402NEW]  129.09 62.74 180 top
RC42  -  [R_0402NEW]  104.96 58.13 90 bottom
RC43  -  [R_0402NEW]  110.95 58.06 0 top
RC44  -  [R_0402NEW]  136.4 80.21 90 top
RC45  -  [R_0402NEW]  101.76 55.82 90 top
RC46  -  [R0402_0OHM-NEW]  138.66 24.81 180 top
RC47  -  [R_0402NEW]  138.66 23.92 180 top
RC48  -  [R_0402NEW]  135.57 21.75 180 top
RC50  -  [R_0402NEW]  137.75 25.73 0 top
RC51  -  [R_0402NEW]  135.02 66.51 0 bottom
RC52  -  [R_0402NEW]  135.02 64.73 0 bottom
RC53  -  [R_0402NEW]  135.02 67.4 0 bottom
RC54  -  [R_0402NEW]  135.02 65.62 0 bottom
RC56  -  [R_0402NEW]  128.44 59.8 180 top
RC57  -  [R_0402NEW]  137.29 81.12 270 top
RC60  -  [R_0402NEW]  127.78 56.35 0 top
RC61  -  [R_0402NEW]  129.86 57.18 270 top
RC63  -  [R_0402NEW]  136.94 80.55 270 bottom
RC64  -  [R_0402NEW]  105.91 82.88 0 top
RC66  -  [R_0402NEW]  147.05 51.47 0 top
RC67  -  [R0402_0OHM-NEW]  148.37 54.26 270 top
RC68  -  [R0402_0OHM-NEW]  146.7 50.57 0 top
RC69  -  [R_0402NEW]  138.52 74.39 270 top
RC70  -  [R_0402NEW]  148.56 50.58 270 top
RC71  -  [R_0402NEW]  137.64 77.04 90 top
RC72  -  [R_0402NEW]  105.36 12.61 180 top
RC73  -  [R_0402NEW]  98.09 19.11 0 bottom
RC74  -  [R_0402NEW]  98.46 10.49 0 top
RC75  -  [R_0402NEW]  149.26 53.35 90 top
RC76  -  [R_0402NEW]  150.22 57.9 90 top
RC78  -  [R_0402NEW]  100.84 57.65 270 top
RC79  -  [R0402_0OHM-NEW]  104.08 9.55 180 top
RC80  -  [R_0402NEW]  101.92 75.84 0 top
RC81  -  [R_0402NEW]  102.83 74.89 180 top
RC82  -  [R_0402NEW]  104.08 8.63 180 top
RC84  -  [R_0402NEW]  101.76 58.58 270 top
RC96  -  [R_0402NEW]  110.71 41.82 270 top
RC97  -  [R_0402NEW]  105.01 36.13 90 bottom
RC98  -  [R_0402NEW]  116.81 43.18 180 top
RC99  -  [R_0402NEW]  150.22 60.56 270 top
RC100  -  [R_0402NEW]  149.69 56.91 270 top
RC120  -  [R_0402NEW]  138.52 75.26 90 top
RC121  -  [R_0402NEW]  138.52 77.04 90 top
RC122  -  [R_0402NEW]  137.66 76.17 270 top
RC123  -  [R_0402NEW]  137.64 73.48 90 top
RC124  -  [R_0402NEW]  93.13 85.8 180 top
RC126  -  [R_0402NEW]  135.51 80.21 90 top
RC128  -  [R_0402NEW]  130.36 81.33 180 bottom
RC129  -  [R0402_0OHM-NEW]  134.63 81.12 270 top
RC130  -  [R_0402NEW]  128.43 68.95 180 top
RC133  -  [R_0402NEW]  116.4 44.17 90 top
RC134  -  [R_0402NEW]  102.83 76.79 180 top
RC140  -  [R_0402NEW]  105.86 46.1 180 bottom
RC141  -  [R_0402NEW]  105.83 47.01 180 bottom
RC143  -  [R_0402NEW]  104.45 11.71 0 top
RD1  -  [R0402_0OHM-NEW]  70.35 14.57 90 bottom
RD2  -  [R0402_0OHM-NEW]  68.45 14.65 0 bottom
RD3  -  [R_0402NEW]  73.61 22.12 180 top
RD4  -  [R_0402NEW]  70.68 22.12 0 top
RD5  -  [R_0402NEW]  70.35 12.75 90 bottom
RD6  -  [R_0402NEW]  80.45 14.99 270 bottom
RD7  -  [R0402_0OHM-NEW]  67.49 14.65 180 bottom
RD8  -  [R_0402NEW]  66.64 82.64 180 top
RD9  -  [R_0402NEW]  71.92 83.94 0 top
RD10  -  [R0402_0OHM-NEW]  56.71 11.36 180 bottom
RD11  -  [R0402_0OHM-NEW]  56.71 14.09 180 bottom
RD12  -  [R0402_0OHM-NEW]  57.64 14.09 0 bottom
RD13  -  [R_0402NEW]  52.94 81.46 270 top
RD14  -  [R_0402NEW]  57.57 80.48 180 top
RE5  -  [R_0402NEW]  270.39 51.4 0 bottom
RE6  -  [R_0402NEW]  258.18 54.61 180 bottom
RE678  -  [R_0402NEW]  289.18 12.75 0 top
RH2  -  [R_0402NEW]  175.25 28.19 270 bottom
RH11  -  [R_0402NEW]  190.78 38.82 270 bottom
RH21  -  [R_0402NEW]  111.97 20.53 0 top
RH22  -  [R_0402NEW]  189.83 38.82 270 bottom
RH23  -  [R_0402NEW]  189.83 40.38 90 bottom
RH24  -  [R_0402NEW]  119.74 21.55 180 top
RH25  -  [R_0402NEW]  178.88 34.1 180 bottom
RH26  -  [R_0402NEW]  180.73 31.24 180 bottom
RH27  -  [R_0402NEW]  176.1 31.33 180 bottom
RH28  -  [R_0402NEW]  186.39 20.14 270 top
RH29  -  [R_0402NEW]  176.03 33.21 180 bottom
RH30  -  [R_0402NEW]  160.53 23.1 0 top
RH31  -  [R_0402NEW]  177.97 32.19 0 bottom
RH35  -  [R_0402NEW]  185.49 22.29 270 top
RH38  -  [R_0402NEW]  172.97 28.65 270 top
RH40  -  [R_0402NEW]  159.67 15.75 270 bottom
RH41  -  [R_0402NEW]  110.19 20.53 0 top
RH42  -  [R_0402NEW]  158.78 15.75 270 bottom
RH43  -  [R_0402NEW]  169.77 15.73 270 bottom
RH44  -  [R_0402NEW]  178.31 17.71 180 bottom
RH45  -  [R_0402NEW]  178.31 15.05 180 bottom
RH46  -  [R_0402NEW]  157.62 15.74 270 bottom
RH47  -  [R_0402NEW]  170.66 15.73 270 bottom
RH48  -  [R_0402NEW]  178.31 16.82 180 bottom
RH49  -  [R_0402NEW]  178.31 14.16 180 bottom
RH50  -  [R_0402NEW]  176.03 34.16 180 bottom
RH52  -  [R_0402NEW]  162.62 15.75 270 bottom
RH53  -  [R_0402NEW]  169.47 22.16 0 top
RH59  -  [R_0402NEW]  169.31 19.39 0 top
RH66  -  [R_0402NEW]  180.59 33.45 90 top
RH74  -  [R_0402NEW]  146.61 29.16 180 top
RH75  -  [R_0402NEW]  146.61 30.1 180 top
RH76  -  [R_0402NEW]  167.18 30.6 180 top
RH77  -  [R_0402NEW]  168.06 30.6 0 top
RH78  -  [R_0402NEW]  154.37 15.43 0 bottom
RH79  -  [R_0402NEW]  153.51 15.43 180 bottom
RH80  -  [R_0402NEW]  176.03 18.66 180 bottom
RH81  -  [R_0402NEW]  177.41 11.37 270 bottom
RH87  -  [R_0402NEW]  161.73 14.83 90 bottom
RH91  -  [R_0402NEW]  142.82 32.99 180 bottom
RH94  -  [R_0402NEW]  178.31 19.62 180 bottom
RH97  -  [R_0402NEW]  175.11 17.71 0 bottom
RH98  -  [R_0402NEW]  177.4 15.93 0 bottom
RH99  -  [R_0402NEW]  161.89 45.51 0 bottom
RH100  -  [R_0402NEW]  160.77 41.68 180 top
RH101  -  [R_0402NEW]  176.03 16.82 180 bottom
RH102  -  [R_0402NEW]  169.79 45.73 0 top
RH103  -  [R_0402NEW]  176.03 15.93 180 bottom
RH105  -  [R_0402NEW]  165.78 43.89 180 top
RH106  -  [R0402_0OHM-NEW]  140.12 17.65 0 bottom
RH107  -  [R0402_0OHM-NEW]  140.12 16.7 0 bottom
RH108  -  [R_0402NEW]  143.26 17.65 180 bottom
RH109  -  [R_0402NEW]  143.26 16.7 180 bottom
RH111  -  [R_0402NEW]  141.9 30.29 0 bottom
RH112  -  [R_0402NEW]  141.9 27.55 0 bottom
RH113  -  [R0402_0OHM-NEW]  176.09 30.22 180 bottom
RH114  -  [R_0402NEW]  178.31 21.5 180 bottom
RH118  -  [R_0402NEW]  179.33 8.89 180 bottom
RH123  -  [R_0402NEW]  167 48.97 270 bottom
RH124  -  [R_0402NEW]  167.86 46.64 270 bottom
RH126  -  [R_0402NEW]  164.25 39.11 0 top
RH127  -  [R_0402NEW]  171.76 27.73 90 top
RH131  -  [R_0402NEW]  165.98 46.62 270 bottom
RH132  -  [R_0402NEW]  165.03 48.05 90 bottom
RH133  -  [R_0402NEW]  165.03 46.62 270 bottom
RH134  -  [R_0402NEW]  165.98 48.05 90 bottom
RH137  -  [R_0402NEW]  165.37 14.83 90 bottom
RH139  -  [R_0402NEW]  176.03 19.62 180 bottom
RH140  -  [R_0402NEW]  176.03 21.5 180 bottom
RH142  -  [R_0402NEW]  176.03 20.57 180 bottom
RH144  -  [R_0402NEW]  180.09 21.5 180 bottom
RH145  -  [R_0402NEW]  174.3 31.15 270 bottom
RH149  -  [R_0402NEW]  150.69 15.49 180 bottom
RH150  -  [R0402_0OHM-NEW]  147.97 15.49 0 bottom
RH151  -  [R_0402NEW]  175.11 32.25 0 bottom
RH152  -  [R_0402NEW]  178.31 20.57 180 bottom
RH158  -  [R_0402NEW]  183.66 22.29 270 top
RH160  -  [R_0402NEW]  169.79 45.7 90 bottom
RH163  -  [R_0402NEW]  170.64 44.36 270 top
RH164  -  [R_0402NEW]  174.64 46.62 180 bottom
RH165  -  [R_0402NEW]  175.88 34.33 180 top
RH166  -  [R_0402NEW]  164.45 14.83 90 bottom
RH170  -  [R_0402NEW]  175.11 20.57 0 top
RH171  -  [R_0402NEW]  186.39 21.39 90 top
RH172  -  [R_0402NEW]  181.87 19.54 90 top
RH173  -  [R_0402NEW]  181.87 21.38 90 top
RH174  -  [R_0402NEW]  184.55 19.23 90 top
RH177  -  [R_0402NEW]  175.11 22.47 0 top
RH178  -  [R_0402NEW]  174.06 35.28 180 top
RH181  -  [R_0402NEW]  182.76 21.39 90 top
RH183  -  [R_0402NEW]  164.98 41.78 180 top
RH197  -  [R0603_0OHM-NEW]  142.74 26.41 180 bottom
RH201  -  [R0402_0OHM-NEW]  163.49 14.83 90 bottom
RH202  -  [R_0402NEW]  172.52 14.82 90 bottom
RH203  -  [R_0402NEW]  180.33 22.31 270 top
RH208  -  [R_0402NEW]  186.01 36.51 180 bottom
RH213  -  [R_0402NEW]  182.36 32.11 90 bottom
RH215  -  [R0603_0OHM-NEW]  176.03 40.31 180 bottom
RH256  -  [R_0402NEW]  176.03 36.43 180 bottom
RH260  -  [R_0402NEW]  170.62 39.38 180 top
RH262  -  [R_0402NEW]  141.25 21.8 90 bottom
RH263  -  [R_0402NEW]  184.56 21.37 90 top
RH266  -  [R_0402NEW]  187.33 19.23 90 top
RH267  -  [R_0402NEW]  148.87 14.54 180 bottom
RH268  -  [R_0402NEW]  166.3 14.82 90 bottom
RH269  -  [R_0402NEW]  173.81 36.22 180 top
RH270  -  [R_0402NEW]  150.03 13.59 180 bottom
RH271  -  [R_0402NEW]  167.19 15.73 270 bottom
RH273  -  [R_0402NEW]  170.85 37.46 180 top
RH278  -  [R_0402NEW]  192.17 21.52 0 bottom
RH279  -  [R_0402NEW]  189.31 24.09 0 bottom
RH283  -  [R_0402NEW]  111.97 21.49 0 top
RH284  -  [R_0402NEW]  117.96 21.55 180 top
RH286  -  [R0402_0OHM-NEW]  176.14 26.45 90 bottom
RH287  -  [R_0402NEW]  176.03 35.56 180 bottom
RH288  -  [R_0603NEW]  177.73 22.29 270 top
RH290  -  [R0402_0OHM-NEW]  161.45 24.48 180 top
RH298  -  [R_0402NEW]  170.16 25.9 0 top
RH299  -  [R_0402NEW]  170.16 26.79 0 top
RH300  -  [R_0402NEW]  176.03 22.42 180 bottom
RH301  -  [R_0402NEW]  177.4 23.36 0 bottom
RH302  -  [R_0402NEW]  183.63 23.48 90 bottom
RH303  -  [R_0402NEW]  180.08 23.39 270 bottom
RH304  -  [R_0402NEW]  177.4 18.66 0 bottom
RH305  -  [R_0402NEW]  296.11 68.4 90 top
RH306  -  [R_0402NEW]  294.96 68.4 90 top
RH309  -  [R0402_0OHM-NEW]  161.89 46.43 0 bottom
RH311  -  [R_0402NEW]  170.74 46.62 270 bottom
RH313  -  [R_0402NEW]  171.7 46.62 270 bottom
RH314  -  [R_0402NEW]  168.84 46.62 270 bottom
RH315  -  [R_0402NEW]  167.95 48.97 270 bottom
RH316  -  [R_0402NEW]  178.63 39.94 180 bottom
RH317  -  [R_0402NEW]  180.27 36.05 90 bottom
RH321  -  [R_0402NEW]  175.99 25.37 90 top
RH323  -  [R0402_0OHM-NEW]  178.31 22.42 180 bottom
RH324  -  [R_0402NEW]  176.03 38.3 180 bottom
RH325  -  [R_0402NEW]  176.03 37.35 180 bottom
RH326  -  [R_0402NEW]  179.24 35.27 180 top
RH327  -  [R_0402NEW]  176.03 39.25 180 bottom
RH328  -  [R_0402NEW]  179.94 36.71 180 top
RH329  -  [R_0402NEW]  175.88 35.28 180 top
RH330  -  [R_0402NEW]  170.34 38.43 180 top
RH331  -  [R_0402NEW]  172.78 46.62 270 bottom
RH332  -  [R_0402NEW]  169.53 43.44 270 top
RH333  -  [R_0402NEW]  169.33 41.33 0 top
RH336  -  [R0402_0OHM-NEW]  182.83 19.41 180 bottom
RH338  -  [R0402_0OHM-NEW]  182.83 20.37 180 bottom
RH341  -  [R_0402NEW]  178.31 25.19 180 bottom
RH342  -  [R_0402NEW]  171.7 48.05 90 bottom
RH343  -  [R_0402NEW]  175.11 25.19 0 bottom
RH344  -  [R_0402NEW]  158.4 37.18 270 top
RH345  -  [R_0402NEW]  175.11 24.43 0 top
RH346  -  [R_0402NEW]  178.31 24.27 180 bottom
RH347  -  [R_0402NEW]  175.11 23.48 0 top
RH348  -  [R_0402NEW]  175.11 24.27 0 bottom
RH349  -  [R_0402NEW]  180.08 24.43 90 bottom
RH350  -  [R_0402NEW]  175.11 23.36 0 bottom
RH351  -  [R_0402NEW]  161.69 37.93 0 top
RH352  -  [R_0402NEW]  161.68 38.83 0 top
RH354  -  [R_0402NEW]  171.54 14.82 90 bottom
RH355  -  [R_0402NEW]  178.88 34.98 180 bottom
RH357  -  [R_0402NEW]  163.44 33.54 270 top
RH358  -  [R_0402NEW]  149.78 14.53 0 bottom
RH359  -  [R0402_0OHM-NEW]  158.65 40.76 90 top
RH360  -  [R0402_0OHM-NEW]  154.86 35.15 0 top
RH363  -  [R_0402NEW]  181.92 21.45 0 bottom
RH364  -  [R_0402NEW]  182.06 25.33 180 bottom
RH365  -  [R_0402NEW]  175.98 27.18 90 top
SW1  -  [SW_SKRBAAE010_4P]  312.62 44.35 270 top
